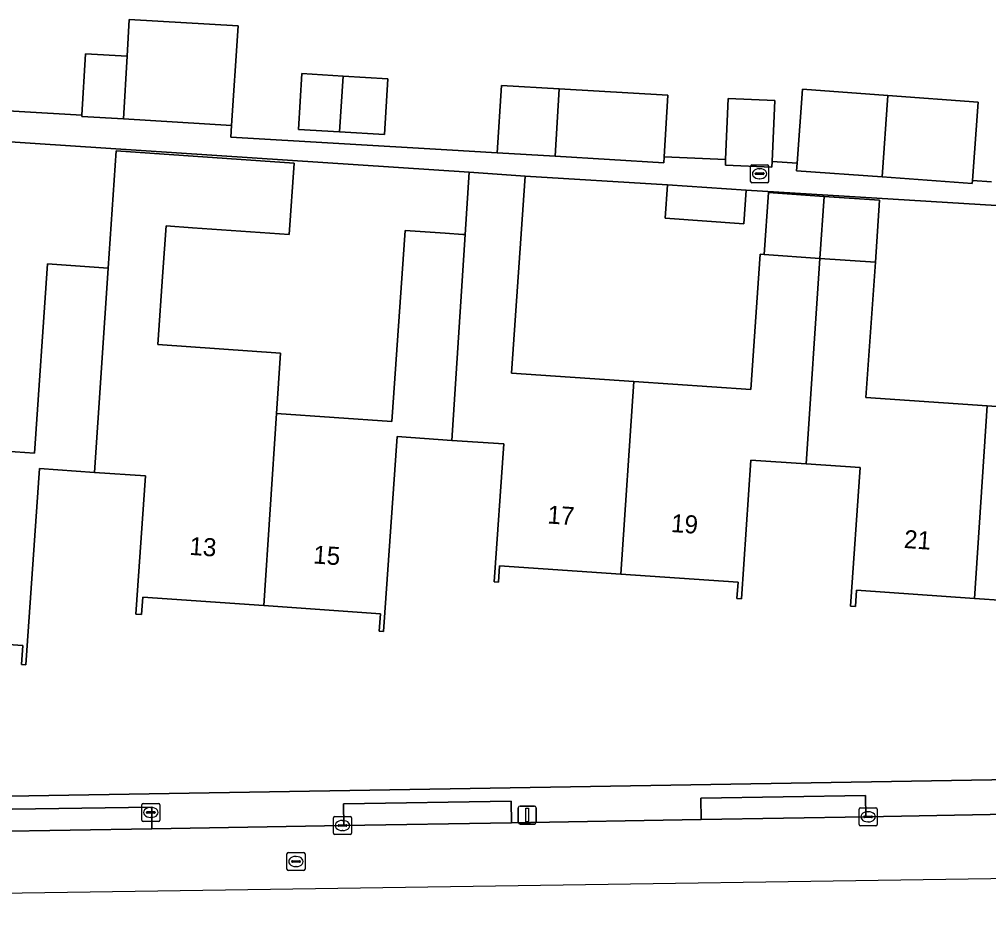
# Model space of a CAD drawing. Extents: x 161848 to 162726, y 385382 to 386521.
# Drawn here: x 162122 to 162175.7, y 385383.2 to 385432.6 of the extents above; entities that cross this region are included whole.
import ezdxf

# ---------------------------------------------------------------- set-up
doc = ezdxf.new("R2010")
doc.units = 0
for name, color, linetype in [('IMGEO_Brandkraan', 7, 'Continuous'), ('IMGEO_Erf', 7, 'Continuous'), ('IMGEO_Kolk', 7, 'Continuous'), ('IMGEO_Lichtmast', 7, 'Continuous'), ('IMGEO_Pand', 7, 'Continuous'), ('IMGEO_Pand_nummerreeks', 7, 'Continuous'), ('IMGEO_Rijbaan_lokaal_open', 7, 'Continuous'), ('IMGEO_Rioolput', 7, 'Continuous'), ('IMGEO_Voetpad_open', 7, 'Continuous')]:
    doc.layers.add(name, color=color, linetype=linetype)

msp = doc.modelspace()

# ---------------------------------------------------------------- linework, layer by layer
at = {"layer": 'IMGEO_Brandkraan'}
for p, q in [((162128.821, 385388.252), (162128.821, 385389.104)), ((162128.896, 385389.178), (162129.748, 385389.178)), ((162129.822, 385389.104), (162129.822, 385388.252)), ((162129.08, 385388.672), (162129.08, 385388.684)), ((162129.518, 385388.635), (162129.12, 385388.635)), ((162129.123, 385388.721), (162129.521, 385388.721)), ((162129.309, 385388.958), (162129.334, 385388.958)), ((162129.564, 385388.684), (162129.564, 385388.672)), ((162129.748, 385388.178), (162128.896, 385388.178)), ((162129.332, 385388.398), (162129.307, 385388.398))]:
    msp.add_line(p, q, dxfattribs=at)
for points in [[(162128.821, 385388.252), (162128.821, 385389.104)], [(162128.896, 385389.178), (162129.748, 385389.178)], [(162129.822, 385389.104), (162129.822, 385388.252)], [(162129.748, 385388.178), (162128.896, 385388.178)]]:
    msp.add_lwpolyline(points, dxfattribs=at)
for centre, radius, start, end in [((162128.898, 385389.102), 0.0765, 91.552, 178.448), ((162128.898, 385389.102), 0.0765, 91.552, 178.448), ((162129.746, 385389.102), 0.0765, 1.552, 88.448), ((162129.746, 385389.102), 0.0765, 1.552, 88.448), ((162129.12, 385388.681), 0.0403, 85.8775, 175.7526), ((162129.117, 385388.671), 0.0366, 178.938, 274.7102), ((162129.521, 385388.678), 0.043, 264.8664, 352.4533), ((162129.525, 385388.683), 0.0386, 1.7309, 96.639), ((162128.898, 385388.254), 0.0765, 181.552, 268.448), ((162128.898, 385388.254), 0.0765, 181.552, 268.448), ((162129.746, 385388.254), 0.0765, 271.552, 358.448), ((162129.746, 385388.254), 0.0765, 271.552, 358.448)]:
    msp.add_arc(centre, radius, start, end, dxfattribs=at)
for centre, major_axis, ratio, start_param, end_param in [((162129.308, 385388.678), (-0.387, 0.002), 0.722429, 4.712389, 7.853982), ((162129.333, 385388.678), (-0.39, 0.002), 0.717154, 1.570796, 4.712389)]:
    msp.add_ellipse(centre, major_axis=major_axis, ratio=ratio, start_param=start_param, end_param=end_param, dxfattribs=at)
at = {"layer": 'IMGEO_Erf'}
for points in [[(162114.743, 385427.947), (162125.504, 385427.309), (162125.707, 385430.72), (162128.008, 385430.584), (162128.129, 385432.62), (162134.153, 385432.263), (162134.136, 385431.977), (162133.791, 385426.747), (162133.748, 385426.099), (162139.734, 385425.744), (162145.726, 385425.388), (162148.502, 385425.223), (162148.752, 385428.959), (162151.949, 385428.769), (162157.96, 385428.413), (162157.758, 385425.005), (162161.16, 385424.859), (162161.305, 385428.231), (162163.885, 385428.12), (162163.739, 385424.747), (162165.121, 385424.646), (162165.422, 385428.748), (162170.14, 385428.403), (162175.153, 385428.035), (162174.835, 385423.698), (162175.897, 385423.62)], [(162116.44, 385409.024), (162122.868, 385408.579), (162123.595, 385419.07), (162126.955, 385418.837), (162127.391, 385425.342), (162137.26, 385424.659), (162136.986, 385420.707), (162131.629, 385421.079), (162130.17, 385421.18), (162129.993, 385418.627), (162129.714, 385414.601), (162136.499, 385414.131), (162136.277, 385410.778), (162142.671, 385410.335), (162143.405, 385420.928), (162145.626, 385420.774), (162146.599, 385420.707), (162146.729, 385420.698), (162146.953, 385424.146), (162078.451, 385428.686)], [(162202.699, 385420.689), (162162.296, 385423.152), (162162.167, 385421.297), (162157.81, 385421.599), (162157.938, 385423.454), (162150.052, 385423.932), (162149.297, 385413.024), (162156.069, 385412.555), (162162.551, 385412.106), (162163.07, 385419.605), (162163.299, 385419.589), (162163.537, 385423.024), (162166.623, 385422.81), (162169.696, 385422.598), (162169.458, 385419.162), (162168.939, 385411.672), (162175.659, 385411.206), (162182.248, 385410.75)], [(162181.529, 385400.081), (162174.951, 385400.537), (162168.419, 385400.989), (162168.357, 385400.088), (162168.079, 385400.107), (162168.611, 385407.781), (162165.621, 385407.988), (162162.566, 385408.2), (162162.034, 385400.509), (162161.793, 385400.526), (162161.856, 385401.433), (162155.363, 385401.883), (162148.638, 385402.349), (162148.576, 385401.441), (162148.34, 385401.457), (162148.869, 385409.094), (162145.99, 385409.293), (162142.965, 385409.503), (162142.217, 385398.701), (162141.974, 385398.718), (162142.041, 385399.691), (162135.577, 385400.139), (162128.87, 385400.604), (162128.803, 385399.644), (162128.496, 385399.665), (162129.027, 385407.321), (162126.197, 385407.517), (162123.156, 385407.728), (162122.403, 385396.856), (162122.15, 385396.873), (162122.223, 385397.922), (162115.731, 385398.372)], [(162063.562, 385388.628), (162063.645, 385388.627), (162208.129, 385391.024)]]:
    msp.add_lwpolyline(points, dxfattribs=at)
msp.add_lwpolyline([(162139.776, 385426.391), (162137.508, 385426.526), (162137.691, 385429.615), (162139.974, 385429.479), (162142.45, 385429.332), (162142.266, 385426.244)], close=True, dxfattribs=at)
at = {"layer": 'IMGEO_Kolk'}
for p, q in [((162168.552, 385388.01), (162168.552, 385388.862)), ((162168.627, 385388.936), (162169.479, 385388.936)), ((162168.854, 385388.479), (162169.252, 385388.479)), ((162169.04, 385388.716), (162169.065, 385388.716)), ((162169.553, 385388.862), (162169.553, 385388.01)), ((162139.44, 385387.525), (162139.44, 385388.377)), ((162139.515, 385388.451), (162140.367, 385388.451)), ((162139.699, 385387.945), (162139.699, 385387.957)), ((162139.742, 385387.994), (162140.14, 385387.994)), ((162139.928, 385388.231), (162139.953, 385388.231)), ((162140.183, 385387.957), (162140.183, 385387.945)), ((162140.441, 385388.377), (162140.441, 385387.525)), ((162169.479, 385387.936), (162168.627, 385387.936)), ((162168.811, 385388.43), (162168.811, 385388.442)), ((162169.249, 385388.393), (162168.851, 385388.393)), ((162169.063, 385388.156), (162169.038, 385388.156)), ((162169.295, 385388.442), (162169.295, 385388.43)), ((162140.367, 385387.451), (162139.515, 385387.451)), ((162140.137, 385387.908), (162139.739, 385387.908)), ((162139.951, 385387.671), (162139.926, 385387.671))]:
    msp.add_line(p, q, dxfattribs=at)
for points in [[(162168.552, 385388.01), (162168.552, 385388.862)], [(162168.627, 385388.936), (162169.479, 385388.936)], [(162169.553, 385388.862), (162169.553, 385388.01)], [(162139.44, 385387.525), (162139.44, 385388.377)], [(162139.515, 385388.451), (162140.367, 385388.451)], [(162140.441, 385388.377), (162140.441, 385387.525)], [(162169.479, 385387.936), (162168.627, 385387.936)], [(162140.367, 385387.451), (162139.515, 385387.451)]]:
    msp.add_lwpolyline(points, dxfattribs=at)
for centre, radius, start, end in [((162168.629, 385388.86), 0.0765, 91.552, 178.448), ((162168.629, 385388.86), 0.0765, 91.552, 178.448), ((162168.851, 385388.439), 0.0403, 85.8775, 175.7526), ((162169.256, 385388.441), 0.0386, 1.7309, 96.639), ((162169.477, 385388.86), 0.0765, 1.552, 88.448), ((162169.477, 385388.86), 0.0765, 1.552, 88.448), ((162139.517, 385388.375), 0.0765, 91.552, 178.448), ((162139.517, 385388.375), 0.0765, 91.552, 178.448), ((162139.739, 385387.954), 0.0403, 85.8775, 175.7526), ((162139.736, 385387.944), 0.0366, 178.938, 274.7102), ((162140.14, 385387.951), 0.043, 264.8664, 352.4533), ((162140.144, 385387.956), 0.0386, 1.7309, 96.639), ((162140.365, 385388.375), 0.0765, 1.552, 88.448), ((162140.365, 385388.375), 0.0765, 1.552, 88.448), ((162168.629, 385388.012), 0.0765, 181.552, 268.448), ((162168.629, 385388.012), 0.0765, 181.552, 268.448), ((162168.848, 385388.429), 0.0366, 178.938, 274.7102), ((162169.252, 385388.436), 0.043, 264.8664, 352.4533), ((162169.477, 385388.012), 0.0765, 271.552, 358.448), ((162169.477, 385388.012), 0.0765, 271.552, 358.448), ((162139.517, 385387.527), 0.0765, 181.552, 268.448), ((162139.517, 385387.527), 0.0765, 181.552, 268.448), ((162140.365, 385387.527), 0.0765, 271.552, 358.448), ((162140.365, 385387.527), 0.0765, 271.552, 358.448)]:
    msp.add_arc(centre, radius, start, end, dxfattribs=at)
for centre, major_axis, ratio, start_param, end_param in [((162169.039, 385388.436), (-0.387, 0.002), 0.722429, 4.712389, 7.853982), ((162169.064, 385388.436), (-0.39, 0.002), 0.717154, 1.570796, 4.712389), ((162139.927, 385387.951), (-0.387, 0.002), 0.722429, 4.712389, 7.853982), ((162139.952, 385387.951), (-0.39, 0.002), 0.717154, 1.570796, 4.712389)]:
    msp.add_ellipse(centre, major_axis=major_axis, ratio=ratio, start_param=start_param, end_param=end_param, dxfattribs=at)
at = {"layer": 'IMGEO_Lichtmast'}
for p, q in [((162149.778, 385389.031), (162150.568, 385389.031)), ((162150.568, 385389.031), (162149.778, 385389.031)), ((162149.678, 385388.131), (162149.678, 385388.931)), ((162149.678, 385388.931), (162149.678, 385388.131)), ((162150.668, 385388.931), (162150.668, 385388.131)), ((162150.668, 385388.131), (162150.668, 385388.931)), ((162150.568, 385388.031), (162149.778, 385388.031)), ((162149.778, 385388.031), (162150.568, 385388.031))]:
    msp.add_line(p, q, dxfattribs=at)
msp.add_lwpolyline([(162150.098, 385388.906), (162150.248, 385388.906), (162150.248, 385388.156), (162150.098, 385388.156), (162150.098, 385388.906)], dxfattribs=at)
for centre, start, end in [((162149.778, 385388.931), 90, 180), ((162149.778, 385388.931), 90, 180), ((162150.568, 385388.931), 0, 90), ((162150.568, 385388.931), 360, 90), ((162149.778, 385388.131), 180, 270), ((162149.778, 385388.131), 180, 270), ((162150.568, 385388.131), 270, 0), ((162150.568, 385388.131), 270, 0)]:
    msp.add_arc(centre, 0.1, start, end, dxfattribs=at)
at = {"layer": 'IMGEO_Pand'}
for points in [[(162134.136, 385431.977), (162134.153, 385432.263), (162128.129, 385432.62), (162128.008, 385430.584), (162127.802, 385427.102), (162133.791, 385426.747)], [(162128.008, 385430.584), (162125.707, 385430.72), (162125.504, 385427.309), (162125.5, 385427.239), (162127.802, 385427.102)], [(162139.974, 385429.479), (162137.691, 385429.615), (162137.508, 385426.526), (162139.776, 385426.391)], [(162139.974, 385429.479), (162139.776, 385426.391), (162142.266, 385426.244), (162142.45, 385429.332)], [(162151.949, 385428.769), (162148.752, 385428.959), (162148.502, 385425.223), (162151.714, 385425.033)], [(162157.96, 385428.413), (162151.949, 385428.769), (162151.714, 385425.033), (162157.738, 385424.676), (162157.758, 385425.005)], [(162170.14, 385428.403), (162165.422, 385428.748), (162165.121, 385424.646), (162165.091, 385424.235), (162169.833, 385423.887)], [(162163.885, 385428.12), (162161.305, 385428.231), (162161.16, 385424.859), (162161.147, 385424.546), (162163.726, 385424.435), (162163.739, 385424.747)], [(162175.153, 385428.035), (162170.14, 385428.403), (162169.833, 385423.887), (162174.822, 385423.522), (162174.835, 385423.698)], [(162136.277, 385410.778), (162136.499, 385414.131), (162129.714, 385414.601), (162129.993, 385418.627), (162130.17, 385421.18), (162131.629, 385421.079), (162136.986, 385420.707), (162137.26, 385424.659), (162127.391, 385425.342), (162126.955, 385418.837), (162126.197, 385407.517), (162129.027, 385407.321), (162128.496, 385399.665), (162128.803, 385399.644), (162128.87, 385400.604), (162135.577, 385400.139)], [(162149.297, 385413.024), (162150.052, 385423.932), (162146.953, 385424.146), (162146.729, 385420.698), (162145.99, 385409.293), (162148.869, 385409.094), (162148.34, 385401.457), (162148.576, 385401.441), (162148.638, 385402.349), (162155.363, 385401.883), (162156.069, 385412.555)], [(162162.296, 385423.152), (162157.938, 385423.454), (162157.81, 385421.599), (162162.167, 385421.297)], [(162166.623, 385422.81), (162163.537, 385423.024), (162163.299, 385419.589), (162166.391, 385419.375)], [(162166.623, 385422.81), (162166.391, 385419.375), (162169.458, 385419.162), (162169.696, 385422.598)], [(162186.169, 385421.418), (162183.621, 385421.595), (162183.391, 385418.254), (162182.771, 385418.297), (162182.248, 385410.75), (162175.659, 385411.206), (162174.951, 385400.537), (162181.529, 385400.081), (162181.461, 385399.1), (162181.734, 385399.081), (162182.274, 385406.874), (162185.19, 385406.672), (162185.947, 385418.077)], [(162146.729, 385420.698), (162146.599, 385420.707), (162145.626, 385420.774), (162143.405, 385420.928), (162142.671, 385410.335), (162136.277, 385410.778), (162135.577, 385400.139), (162142.041, 385399.691), (162141.974, 385398.718), (162142.217, 385398.701), (162142.965, 385409.503), (162145.99, 385409.293)], [(162115.731, 385398.372), (162122.223, 385397.922), (162122.15, 385396.873), (162122.403, 385396.856), (162123.156, 385407.728), (162126.197, 385407.517), (162126.955, 385418.837), (162123.595, 385419.07), (162122.868, 385408.579), (162116.44, 385409.024)], [(162166.391, 385419.375), (162163.299, 385419.589), (162163.07, 385419.605), (162162.551, 385412.106), (162156.069, 385412.555), (162155.363, 385401.883), (162161.856, 385401.433), (162161.793, 385400.526), (162162.034, 385400.509), (162162.566, 385408.2), (162165.621, 385407.988)], [(162175.659, 385411.206), (162168.939, 385411.672), (162169.458, 385419.162), (162166.391, 385419.375), (162165.621, 385407.988), (162168.611, 385407.781), (162168.079, 385400.107), (162168.357, 385400.088), (162168.419, 385400.989), (162174.951, 385400.537)]]:
    msp.add_lwpolyline(points, close=True, dxfattribs=at)
at = {"layer": 'IMGEO_Rijbaan_lokaal_open'}
for points in [[(162189.582, 385385.225), (162189.582, 385385.225), (162189.49, 385388.764), (162188.726, 385388.73), (162179.744, 385388.632), (162168.923, 385388.434), (162159.81, 385388.278), (162149.297, 385388.097), (162140.02, 385387.952), (162129.374, 385387.774), (162120.31, 385387.623), (162109.802, 385387.486), (162100.697, 385387.385), (162089.885, 385387.193), (162080.873, 385387.09), (162070.989, 385386.922), (162063.795, 385386.826), (162063.367, 385386.841)], [(162055.943, 385383.237), (162132.196, 385384.371), (162189.582, 385385.225)]]:
    msp.add_lwpolyline(points, dxfattribs=at)
at = {"layer": 'IMGEO_Rioolput'}
for p, q in [((162162.546, 385423.642), (162162.546, 385424.494)), ((162162.621, 385424.568), (162163.473, 385424.568)), ((162163.547, 385424.494), (162163.547, 385423.642)), ((162162.805, 385424.062), (162162.805, 385424.074)), ((162163.243, 385424.025), (162162.845, 385424.025)), ((162162.848, 385424.111), (162163.246, 385424.111)), ((162163.034, 385424.348), (162163.059, 385424.348)), ((162163.289, 385424.074), (162163.289, 385424.062)), ((162163.473, 385423.568), (162162.621, 385423.568)), ((162163.057, 385423.788), (162163.032, 385423.788)), ((162136.861, 385385.531), (162136.861, 385386.383)), ((162136.936, 385386.457), (162137.788, 385386.457)), ((162137.862, 385386.383), (162137.862, 385385.531)), ((162137.12, 385385.951), (162137.12, 385385.963)), ((162137.558, 385385.914), (162137.16, 385385.914)), ((162137.163, 385386), (162137.561, 385386)), ((162137.349, 385386.237), (162137.374, 385386.237)), ((162137.604, 385385.963), (162137.604, 385385.951)), ((162137.788, 385385.457), (162136.936, 385385.457)), ((162137.372, 385385.677), (162137.347, 385385.677))]:
    msp.add_line(p, q, dxfattribs=at)
for points in [[(162162.546, 385423.642), (162162.546, 385424.494)], [(162162.621, 385424.568), (162163.473, 385424.568)], [(162163.547, 385424.494), (162163.547, 385423.642)], [(162163.473, 385423.568), (162162.621, 385423.568)], [(162136.861, 385385.531), (162136.861, 385386.383)], [(162136.936, 385386.457), (162137.788, 385386.457)], [(162137.862, 385386.383), (162137.862, 385385.531)], [(162137.788, 385385.457), (162136.936, 385385.457)]]:
    msp.add_lwpolyline(points, dxfattribs=at)
for centre, radius, start, end in [((162162.623, 385424.492), 0.0765, 91.552, 178.448), ((162162.623, 385424.492), 0.0765, 91.552, 178.448), ((162163.471, 385424.492), 0.0765, 1.552, 88.448), ((162163.471, 385424.492), 0.0765, 1.552, 88.448), ((162162.845, 385424.071), 0.0403, 85.8775, 175.7526), ((162162.842, 385424.061), 0.0366, 178.938, 274.7102), ((162163.246, 385424.068), 0.043, 264.8664, 352.4533), ((162163.25, 385424.073), 0.0386, 1.7309, 96.639), ((162162.623, 385423.644), 0.0765, 181.552, 268.448), ((162162.623, 385423.644), 0.0765, 181.552, 268.448), ((162163.471, 385423.644), 0.0765, 271.552, 358.448), ((162163.471, 385423.644), 0.0765, 271.552, 358.448), ((162136.938, 385386.381), 0.0765, 91.552, 178.448), ((162136.938, 385386.381), 0.0765, 91.552, 178.448), ((162137.786, 385386.381), 0.0765, 1.552, 88.448), ((162137.786, 385386.381), 0.0765, 1.552, 88.448), ((162137.16, 385385.96), 0.0403, 85.8775, 175.7526), ((162137.157, 385385.95), 0.0366, 178.938, 274.7102), ((162137.561, 385385.957), 0.043, 264.8664, 352.4533), ((162137.565, 385385.962), 0.0386, 1.7309, 96.639), ((162136.938, 385385.533), 0.0765, 181.552, 268.448), ((162136.938, 385385.533), 0.0765, 181.552, 268.448), ((162137.786, 385385.533), 0.0765, 271.552, 358.448), ((162137.786, 385385.533), 0.0765, 271.552, 358.448)]:
    msp.add_arc(centre, radius, start, end, dxfattribs=at)
for centre, major_axis, ratio, start_param, end_param in [((162163.033, 385424.068), (-0.387, 0.002), 0.722429, 4.712389, 7.853982), ((162163.058, 385424.068), (-0.39, 0.002), 0.717154, 1.570796, 4.712389), ((162137.348, 385385.957), (-0.387, 0.002), 0.722429, 4.712389, 7.853982), ((162137.373, 385385.957), (-0.39, 0.002), 0.717154, 1.570796, 4.712389)]:
    msp.add_ellipse(centre, major_axis=major_axis, ratio=ratio, start_param=start_param, end_param=end_param, dxfattribs=at)
at = {"layer": 'IMGEO_Voetpad_open'}
for points in [[(162078.451, 385428.686), (162146.953, 385424.146), (162150.052, 385423.932), (162157.938, 385423.454), (162162.296, 385423.152), (162202.699, 385420.689)], [(162175.897, 385423.62), (162174.835, 385423.698), (162174.822, 385423.522), (162169.833, 385423.887), (162165.091, 385424.235), (162165.121, 385424.646), (162163.739, 385424.747), (162163.726, 385424.435), (162161.147, 385424.546), (162161.16, 385424.859), (162157.758, 385425.005), (162157.738, 385424.676), (162151.714, 385425.033), (162148.502, 385425.223), (162145.726, 385425.388), (162139.734, 385425.744), (162133.748, 385426.099), (162133.791, 385426.747), (162127.802, 385427.102), (162125.5, 385427.239), (162125.504, 385427.309), (162114.743, 385427.947)], [(162214.289, 385391.126), (162208.129, 385391.024), (162063.645, 385388.627), (162063.562, 385388.628), (162059.733, 385388.652)], [(162159.789, 385389.475), (162168.907, 385389.617), (162168.923, 385388.434), (162179.744, 385388.632), (162179.733, 385389.813), (162188.697, 385389.937), (162188.726, 385388.73), (162189.49, 385388.764), (162210.187, 385389.095)], [(162063.367, 385386.841), (162063.795, 385386.826), (162063.717, 385388.023), (162070.949, 385388.106), (162070.989, 385386.922), (162080.873, 385387.09), (162080.878, 385388.225), (162089.857, 385388.391), (162089.885, 385387.193), (162100.697, 385387.385), (162100.651, 385388.586), (162109.82, 385388.696), (162109.802, 385387.486), (162120.31, 385387.623), (162120.322, 385388.848), (162129.374, 385388.972), (162129.374, 385387.774), (162140.02, 385387.952), (162139.998, 385389.158), (162149.283, 385389.298), (162149.297, 385388.097), (162159.81, 385388.278), (162159.789, 385389.475)]]:
    msp.add_lwpolyline(points, dxfattribs=at)
for points in [[(162159.81, 385388.278), (162168.923, 385388.434), (162168.907, 385389.617), (162159.789, 385389.475)], [(162140.02, 385387.952), (162149.297, 385388.097), (162149.283, 385389.298), (162139.998, 385389.158)], [(162129.374, 385387.774), (162129.374, 385388.972), (162120.322, 385388.848), (162120.31, 385387.623)]]:
    msp.add_lwpolyline(points, close=True, dxfattribs=at)

# ---------------------------------------------------------------- texts
at = {"layer": 'IMGEO_Pand_nummerreeks'}
for s, rotation, p in [('17', 356.0351, (162151.267, 385404.693)), ('19', 356.0351, (162158.114, 385404.219)), ('21', 356.038, (162171.019, 385403.336)), ('13', 356.0351, (162131.434, 385402.953)), ('15', 356.0351, (162138.294, 385402.477))]:
    msp.add_text(s, height=1, rotation=rotation, dxfattribs=at).set_placement(p)

doc.saveas('drawing.dxf')
